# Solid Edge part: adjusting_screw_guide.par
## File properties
Title: Adjusting screw guide
Author: vicky raina
Template: Normal.par
Last saved by: Robert a Rhodes jr
Revision: 2
Application: Solid Edge
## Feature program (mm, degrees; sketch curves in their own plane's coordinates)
sketch for "unnamed Protrusion 1" plane through (0, 0, 0) normal (0, -1, 0) x-axis (1, 0, 0)
  circle centre (0, 0) radius 7.9375
extrude "unnamed Protrusion 1" add finite 63.5 along +normal
sketch for "unnamed Protrusion 2" plane through (0, -63.5, 0) normal (0, -1, 0) x-axis (1, 0, 0)
  circle centre (0, 0) radius 6.3119
extrude "unnamed Protrusion 2" add finite 76.2 along +normal
chamfer "unnamed Chamfer 1"
sketch for "unnamed Cutout 1" plane through (0, 0, 0) normal (0, 0, 1) x-axis (1, 0, 0)
  line (1.1811, 0) -> (1.1811, -4.7498)
  line (1.1811, -4.7498) -> (-1.1811, -4.7498)
  line (-1.1811, -4.7498) -> (-1.1811, 0)
  line (-1.1811, 0) -> (1.1811, 0)
extrude "unnamed Cutout 1" cut finite 101.6 symmetric
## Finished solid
Body 1: solid body, 10 faces, 16 edges, 8 vertices.
  Faces by surface: plane 7, cylinder 2, cone 1
  Edges by curve: circle 8, line 8
Bounding box of the edges (mm): 15.875 x 139.700 x 15.875, from (-7.9375, -139.7, -7.9375) to (7.9375, 0, 7.9375).
Cylindrical faces by radius (mm): R6.3119 x1, R7.9375 x1
Conical faces (half-angle, radius in mm at the cone's reference point): 45 deg R6.3119 x1
Planar faces by outward normal: +x 1, +y 3, -x 1, -y 2
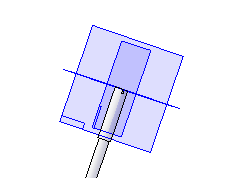
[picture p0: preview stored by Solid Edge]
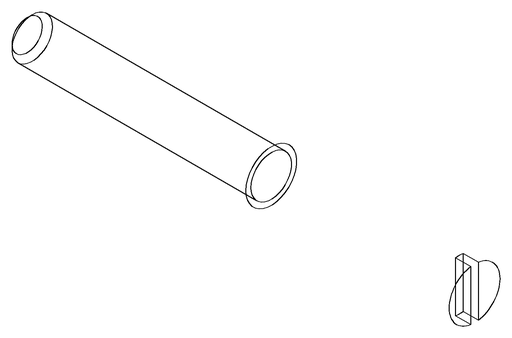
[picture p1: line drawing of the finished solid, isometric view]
